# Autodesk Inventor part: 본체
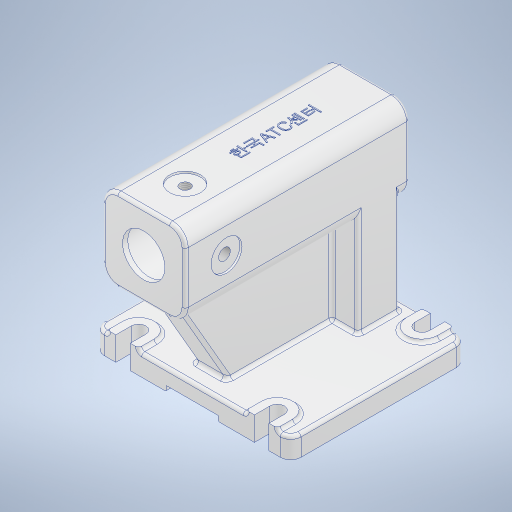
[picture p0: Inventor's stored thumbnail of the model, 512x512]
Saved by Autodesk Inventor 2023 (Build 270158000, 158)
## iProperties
Created: 2024-07
Part Number: 본체
Material: 알루미늄 6061
Document SubType Name: Modeling
Designer: home
Density: 2.7 g/cm^3
Appearance: 알루미늄 - 평지
Mass: 6291.54 g
Surface Area: 2382.6 cm^2
Volume: 2330.2 cm^3
Author: home
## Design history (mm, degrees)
sketch "스케치2"
  geometry: L1 (-40, 40)-(40, 40); L2 (40, 40)-(40, -40); L3 (40, -40)-(-40, -40); L4 (-40, -40)-(-40, 40); L5 (-40, 40)-(40, -40); L6 (40, 40)-(-40, -40); C1 r 20.5 at (0, 0); 1 further point
  constraints: 12 end point, 2 midpoint, 2 parallel, 1 centre point, 1 coincident, 1 horizontal, 1 perpendicular
  dimensions: "d0" = 80 distance of L1.start L1.end; "d1" = 80 distance of L1.end L2.end; "d2" = 41 diameter of C1
extrude "돌출1" new body sketch "스케치2" distance "d3" = 217; taper "d4" = 0 deg
sketch "스케치3"
  geometry: C1 r 20.5 at (0, 0) reference; C2 r 26 at (0, 0)
  constraints: 1 centre point, 1 coincident
  dimensions: "d5" = 52 diameter of C2
extrude "돌출2" cut sketch "스케치3" distance "d6" = 212; taper "d7" = 0 deg
node "작업 평면1"
sketch "스케치4"
  geometry: L1 (80, 0)-(0, 0) reference; L2 (0, 0)-(0, 217) reference; L3 (80, 217)-(0, 217) reference; L4 (80, 0)-(80, 217) reference; L5 (-55, 0)-(135, 0); L6 (135, 0)-(135, 170); L7 (135, 170)-(-55, 170); L8 (-55, 170)-(-55, 0); L9 (40, 0)-(40, 245.035); 2 further points
  constraints: 10 end point, 2 parallel, 1 horizontal, 1 horizontal alignment, 1 perpendicular, 1 vertical
  dimensions: "d9" = 170 distance of L5.end L6.end; "d10" = 190 distance of L5.start L5.end; "d12" = 190 diameter of L8 L9
extrude "돌출3" join sketch "스케치4" distance "d13" = 23; taper "d14" = 0 deg
sketch "스케치5"
  geometry: L1 (-55, -170)-(135, -170) reference; L2 (135, -170)-(135, 0) reference; L3 (-55, 0)-(-55, -170) reference; L4 (80, 0)-(0, 0) reference; L5 (-42, -15)-(-42, 0); L6 (-12, -15)-(-12, 0); L7 (92, -15)-(92, 0); L8 (122, -15)-(122, 0); L9 (-42, -155)-(-42, -170); L10 (-12, -155)-(-12, -170); L11 (92, -155)-(92, -170); L12 (122, -155)-(122, -170); A1 r 15 centre (-27, -15) between (-42, -15) and (-12, -15); A2 r 15 centre (107, -15) between (92, -15) and (122, -15); A3 r 15 centre (107, -155) between (122, -155) and (92, -155); A4 r 15 centre (-27, -155) between (-12, -155) and (-42, -155); 2 further points
  constraints: 16 end point, 8 point on circle, 8 tangent, 4 centre point, 4 perpendicular, 4 point on line, 4 vertical, 3 equal radius, 2 horizontal alignment, 2 vertical alignment, 1 midpoint, 5 other
  dimensions: "d15" = 30 diameter of A1; "d16" = 134 distance of A2.centre A1.centre; "d17" = 67 horizontal distance of point (40, 0) A1.centre (= 0.5 x d16); "d18" = 15 dimension on A2.centre; "d19" = 15 distance from line of L1 A3.centre
extrude "돌출4" cut sketch "스케치5" distance "d20" = 3; taper "d21" = 0 deg
sketch "스케치6"
  geometry: L1 (-42, -170)-(-12, -170) reference; L2 (-42, 0)-(-42, -15) reference; L3 (-12, -15)-(-12, 0) reference; L4 (-12, 0)-(-42, 0) reference; L5 (92, 0)-(92, -15) reference; L6 (122, -15)-(122, 0) reference; L7 (122, 0)-(92, 0) reference; L8 (92, -155)-(92, -170) reference; L9 (92, -170)-(122, -170) reference; L10 (122, -170)-(122, -155) reference; L11 (-34, -15)-(-34, 0); L12 (-20, -15)-(-20, 0); L13 (100, -15)-(100, 0); L14 (114, 0)-(114, -15); L15 (100, -155)-(100, -170); L16 (114, -170)-(114, -155); L17 (-34, -155)-(-34, -170); L18 (-20, -170)-(-20, -155); L19 (-55, -170)-(-55, 0) reference; L20 (135, 0)-(135, -170) reference; A1 r 15 centre (-27, -155) between (-12, -155) and (-42, -155) reference; A2 r 15 centre (-27, -15) between (-42, -15) and (-12, -15) reference; A3 r 15 centre (107, -15) between (92, -15) and (122, -15) reference; A4 r 15 centre (107, -155) between (122, -155) and (92, -155) reference; A5 r 7 centre (-27, -15) between (-34, -15) and (-20, -15); A6 r 7 centre (107, -15) between (100, -15) and (114, -15); A7 r 7 centre (107, -155) between (114, -155) and (100, -155); A8 r 7 centre (-27, -155) between (-20, -155) and (-34, -155); 5 further points
  constraints: 16 end point, 8 point on circle, 5 point on line, 5 vertical alignment, 4 centre point, 1 midpoint, 1 parallel, 1 perpendicular, 4 other
  dimensions: "d22" = 7 radius of A5; "d24" = 7 radius of A6; "d25" = 7 radius of A7; "d26" = 7 radius of A8; "d27" = 21 distance between parallel lines of L19 L17; "d29" = 14 distance between parallel lines of L17 L18; "d30" = 21 distance between parallel lines of L20 L16; "d31" = 14 distance between parallel lines of L16 L15
extrude "돌출5" cut sketch "스케치6" extent not by distance; stored distance "d32" = 3; taper "d33" = 0 deg
sketch "스케치7"
  geometry: L1 (-40, 0)-(40, 0) reference; L2 (40, 0)-(40, 217) reference; L3 (-40, 217)-(40, 217) reference; L4 (-40, 0)-(-40, 217) reference; L5 (-40, 202)-(-130, 150.038); L6 (-130, 170)-(-130, 0) reference; L7 (-177.481, 10)-(-40, 10); L8 (-40, 10)-(-40, 202); L9 (-150, 0)-(-130, 0) reference; 4 further points
  constraints: 6 end point, 2 perpendicular, 1 point on line, 1 vertical alignment
  dimensions: "d34" = 120 deg angle of L6 L5; "d35" = 10 distance between parallel lines of L9 L7; "d36" = 15 distance from line of L3 L5.start
extrude "돌출6" join sketch "스케치7" stored distance "d37" = 30; taper "d38" = 0 deg
sketch "스케치8"
  geometry: L1 (-40, 202)-(-40, 10) reference; L2 (-40, 202)-(-130, 150.038) reference; L3 (-130, 10)-(-130, 150.038) reference; L4 (-130, 10)-(-40, 10) reference; L5 (-40, 10)-(-130, 10); L6 (-130, 10)-(-130, 50); L7 (-130, 50)-(-40, 50); L8 (-40, 50)-(-40, 10); 2 further points
  constraints: 8 end point, 2 parallel, 1 horizontal, 1 perpendicular, 1 point on line
  dimensions: "d39" = 40 distance between parallel lines of L4 L7
extrude "돌출7" join sketch "스케치8" stored distance "d40" = 80; taper "d41" = 0 deg
sketch "스케치9"
  geometry: C1 r 26 at (0, 0) reference; A1 r 32 centre (0, 0) between (0, 32) and (-32, 0); 2 further points
  constraints: 4 point on circle, 1 centre point, 1 coincident
  dimensions: "d42" = 64 diameter of A1
hole "구멍1" sketch "스케치9" at (0, 32), (-32, 0), (0, -32), (32, 0) diameter "d43" = 4.917; stored, may be unused: countersink angle "d47" = 90 deg, drill point angle "d49" = 118 deg; dims "d44" = 12, "d45" = 19.05, "d46" = 4.775, "d48" = 14
sketch "스케치10"
  geometry: L1 (26, 212)-(-26, 212) reference; L2 (26, 0)-(-26, 0) reference; L3 (-40, 0)-(40, 0) reference; L4 (40, 0)-(40, 217) reference; L5 (-40, 217)-(40, 217) reference; L6 (-40, 50)-(-40, 217) reference; L7 (-40, 50)-(-130, 50) reference; L8 (-130, 10)-(-130, 50) reference; L9 (-130, 10)-(-40, 10) reference; L10 (-40, 0)-(-40, 10) reference; L11 (0, 0)-(0, 30.643); L12 (27.155, 0)-(26, 2); L13 (26, 0)-(26, 212) reference; L14 (26, 0)-(27.155, 0); L15 (0, 4.485)-(0, -18.006); 1 further point
  constraints: 8 end point, 3 point on line, 2 vertical, 1 perpendicular
  dimensions: "d51" = 30 deg angle of L13 L12; "d52" = 2 distance from line of L14 L12.end
revolve "회전1" sketch "스케치10" stored, may be unused: angle "d53" = 90 deg
sketch "스케치11"
  geometry: L1 (80, 0)-(0, 0) reference; L2 (40, 0)-(40, -243.457); 1 further point
  constraints: 2 end point, 1 point on line, 1 vertical
  dimensions: "d54" = 177 distance from line of L1 point (40, -177)
hole "구멍2" sketch "스케치11" at (40, -177) diameter "d55" = 10.106; stored, may be unused: countersink angle "d59" = 90 deg, drill point angle "d61" = 118 deg; dims "d56" = 24, "d57" = 30, "d58" = 2, "d60" = 50.25
sketch "스케치12"
  geometry: L1 (0, 0)-(0, 80) reference; L2 (-217, 0)-(-217, 80) reference; L3 (-217, 40)-(-124.786, 40); 2 further points
  constraints: 2 end point, 1 horizontal, 1 midpoint, 1 point on line
  dimensions: "d62" = 177 distance from line of L1 point (-177, 40)
hole "구멍3" sketch "스케치12" at (-177, 40) diameter "d63" = 11.45873; stored, may be unused: countersink angle "d67" = 90 deg, drill point angle "d69" = 118 deg; dims "d64" = 24, "d65" = 30, "d66" = 2, "d68" = 50.25
fillet "모깎기1" dims "d70" = 15
fillet "모깎기3" dims "d72" = 1
fillet "모깎기4" dims "d73" = 2
fillet "모깎기5" dims "d74" = 3
fillet "모깎기6" dims "d75" = 10
fillet "모깎기7" dims "d76" = 3
fillet "모깎기8" dims "d77" = 3
sketch "스케치13"
  geometry: L1 (120, 0)-(0, 0) reference; L2 (35, 0)-(85, 0); L3 (85, 0)-(85, 5); L4 (85, 5)-(35, 5); L5 (35, 5)-(35, 0); 4 further points
  constraints: 8 end point, 2 midpoint, 2 parallel, 1 horizontal, 1 perpendicular, 1 point on line
  dimensions: "d78" = 50 distance of L3.end L4.end; "d79" = 5 distance of L4.end L2.start; "d80" = 25 horizontal distance of point (60, 0) point (35, 2.5) (= 0.5 x d78)
extrude "돌출8" cut sketch "스케치13" extent not by distance; stored distance "d81" = 0; taper "d82" = 0 deg
chamfer "모따기1" distance "d83" = 1; stored, may be unused: second distance "d84" = 2, angle "d85" = 45 deg
fillet "모깎기9" dims "d86" = 3
sketch "스케치14"
  geometry: L1 (74, 3)-(-24, 3) reference; 2 further points
  constraints: 1 vertical alignment, 1 other
  dimensions: "d87" = 90 distance from line of L1 point (25, -87)
feature "엠보싱1" sketch "스케치14" dims "d0" = 80, "d1" = 80, "d88" = 0.5, "d89" = 0
fillet "모깎기10" dims "d90" = 3
feature "ӻ耀ӽ耀ӿ耀ԁ耀ԃ耀ԅ耀ԇ耀ԉ耀" dims "d0" = 80, "d1" = 80, "d2" = 41, "d3" = 217, "d4" = 0, "d5" = 52, "d6" = 212, "d7" = 0, "d8" = 110, "d9" = 170, "d10" = 190, "d12" = 190, "d13" = 23, "d14" = 0, "d15" = 30, "d16" = 134, "d17" = 67 (= 0.5 x d16), "d18" = 15, "d19" = 15, "d20" = 3, "d21" = 0, "d22" = 7, "d24" = 7, "d25" = 7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
node "솔리드1"
mirror "미러1"
node "투영된 루프1"
node "투영된 루프2"
node "투영된 루프3"
node "투영된 루프4"
node "투영된 루프5"
node "투영된 루프6"
node "투영된 루프7"
node "투영된 루프8"
feature "A9D066F2-1C7D-4E18-AEED-F7BC21143FA4" dims "d43" = 4.917, "d44" = 12, "d45" = 19.05, "d46" = 4.775, "d47" = 90 deg, "d48" = 14, "d49" = 118 deg
